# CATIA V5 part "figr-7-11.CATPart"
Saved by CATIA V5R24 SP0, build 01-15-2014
Part number: Part1
Bounding box of the stored display mesh (mm): x -50 to 50, y -62.5 to 112.5, z 0 to 100
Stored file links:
  D:\KAVITA\CATIA V5-6R2014 Project_ Kavita\CATIA V5-6R2014_partfiles\Partfiles\c07_catia_v5-6r2014_prt\figr-7-11.CATPart
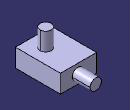
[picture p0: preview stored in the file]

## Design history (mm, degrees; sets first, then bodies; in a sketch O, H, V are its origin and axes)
Body1 (main body)
  Sketch1 on xy-plane, origin (0, 0, 0), H (1, 0, 0), V (0, 1, 0)
    line L1 (-50, 62.5) -> (50, 62.5)
    line L2 (50, 62.5) -> (50, -62.5)
    line L3 (50, -62.5) -> (-50, -62.5)
    line L4 (-50, -62.5) -> (-50, 62.5)
    axis line L5 (50, -62.5) -> (-50, 62.5)
    length L3 = 100
    length L2 = 125
    horizontal: L1 H, L3 H
    vertical: L2 V, L4 V
    midpoint: O L5
  Pad1: profile Sketch1, direction (0, 0, 1), length 50
  Sketch2 on face of Pad1, origin (0, 0, 50), H (1, 0, 0), V (0, 1, 0)
    circle A1 centre (8.7691, -19.7725) radius 15.5717
  Pad2: profile Sketch2, direction (0, 0, 1), length 50
  Sketch3 on face of Pad1, origin (0, 62.5, 112.5), H (1, 0, 0), V (0, 0, -1)
    circle A1 centre (2.1924, 87.7667) radius 15.5717
  Pad3: profile Sketch3, direction (0, 1, 0), length 50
